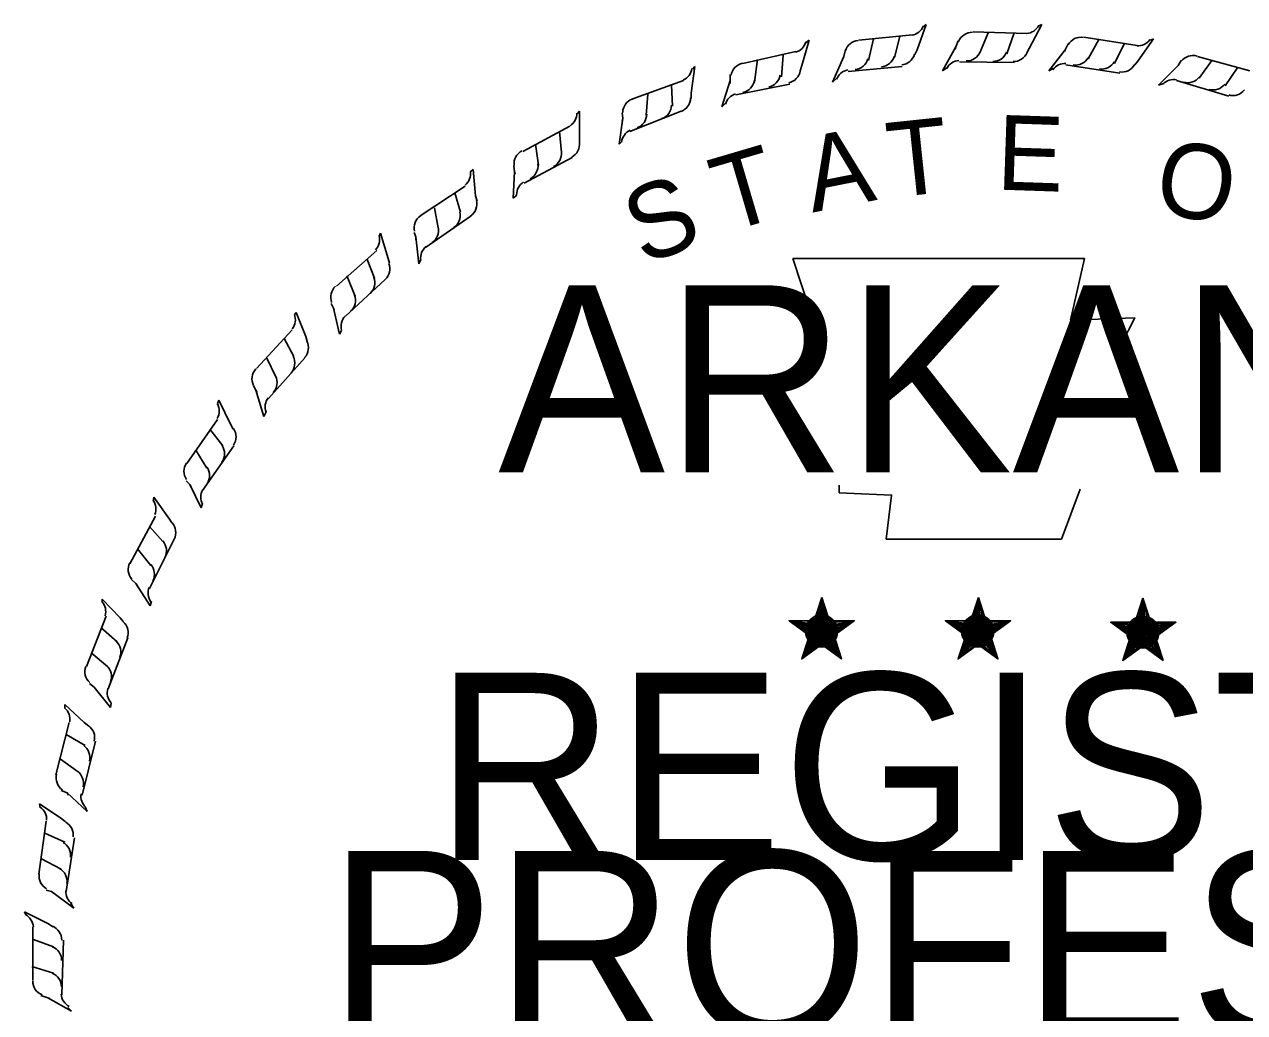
# Model space of a CAD drawing. Extents: x -193 to 149, y 507 to 725.
# Drawn here: x 54.01 to 66.24, y 530.25 to 540.16 of the extents above; entities that cross this region are included whole.
import ezdxf

# ---------------------------------------------------------------- set-up
doc = ezdxf.new("R2010")
doc.units = 0
doc.layers.add('Border 2660-Hwy18 - Stamp-ChrisC', color=7, linetype='Continuous')

msp = doc.modelspace()

# ---------------------------------------------------------------- linework, layer by layer
at = {"layer": 'Border 2660-Hwy18 - Stamp-ChrisC'}
for p, q in [((62.37, 540), (62.91, 540.053)), ((62.73, 539.828), (62.782, 540.038)), ((62.955, 539.903), (63.045, 540.158)), ((63.045, 540.158), (63.015, 540.135)), ((63.517, 540.083), (64.057, 540.068)), ((63.585, 539.873), (63.667, 540.075)), ((63.855, 539.865), (63.93, 540.075)), ((64.08, 539.918), (64.207, 540.158)), ((64.207, 540.158), (64.177, 540.143)), ((61.8, 539.745), (61.875, 540)), ((61.875, 540), (61.845, 539.978)), ((62.467, 539.798), (62.52, 540.015)), ((63.345, 539.933), (63.21, 539.693)), ((63.345, 539.933), (63.337, 539.91)), ((63.367, 539.993), (63.345, 539.933)), ((64.057, 539.873), (64.08, 539.918)), ((64.47, 539.963), (64.44, 539.903)), ((64.627, 540.03), (65.16, 539.948)), ((64.672, 539.813), (64.777, 540.008)), ((64.935, 539.768), (65.032, 539.963)), ((65.167, 539.79), (65.325, 540.015)), ((65.325, 540.015), (65.295, 540)), ((61.207, 539.768), (61.74, 539.888)), ((61.327, 539.58), (61.357, 539.805)), ((61.597, 539.633), (61.612, 539.85)), ((62.22, 539.835), (62.107, 539.58)), ((62.22, 539.835), (62.212, 539.813)), ((62.235, 539.895), (62.22, 539.835)), ((62.932, 539.858), (62.955, 539.903)), ((64.44, 539.903), (64.275, 539.693)), ((64.44, 539.903), (64.432, 539.888)), ((65.602, 539.798), (65.572, 539.745)), ((65.767, 539.835), (66.292, 539.693)), ((65.782, 539.618), (65.91, 539.798)), ((60.69, 539.468), (60.727, 539.738)), ((60.727, 539.738), (60.705, 539.708)), ((61.785, 539.693), (61.8, 539.745)), ((62.805, 539.738), (62.265, 539.685)), ((63.21, 539.693), (63.255, 539.723)), ((63.93, 539.775), (63.382, 539.783)), ((64.275, 539.693), (64.32, 539.715)), ((64.987, 539.67), (64.447, 539.753)), ((65.137, 539.753), (65.167, 539.79)), ((65.572, 539.745), (65.377, 539.55)), ((65.572, 539.745), (65.557, 539.73)), ((66.045, 539.543), (66.172, 539.73)), ((60.097, 539.408), (60.615, 539.595)), ((60.502, 539.34), (60.495, 539.55)), ((61.08, 539.595), (60.997, 539.333)), ((61.08, 539.655), (61.08, 539.595)), ((61.08, 539.595), (61.08, 539.565)), ((61.68, 539.558), (61.14, 539.453)), ((62.107, 539.58), (62.152, 539.618)), ((65.377, 539.55), (65.43, 539.565)), ((66.082, 539.438), (65.557, 539.595)), ((60.24, 539.25), (60.255, 539.46)), ((60.69, 539.415), (60.69, 539.468)), ((60.997, 539.333), (61.035, 539.37)), ((59.572, 539.288), (59.55, 539.265)), ((59.572, 539.025), (59.572, 539.288)), ((60.007, 539.22), (59.97, 538.958)), ((60, 539.273), (60.007, 539.22)), ((60.007, 539.22), (60, 539.19)), ((60.592, 539.288), (60.075, 539.085)), ((59.002, 538.883), (59.475, 539.138)), ((59.392, 538.875), (59.37, 539.085)), ((59.16, 538.748), (59.13, 538.958)), ((59.572, 538.973), (59.572, 539.025)), ((59.97, 538.958), (60, 538.988)), ((59.497, 538.823), (59.017, 538.568)), ((58.507, 538.703), (58.477, 538.68)), ((58.53, 538.44), (58.507, 538.703)), ((58.912, 538.74), (58.92, 538.68)), ((58.92, 538.68), (58.905, 538.418)), ((58.92, 538.68), (58.927, 538.658)), ((57.975, 538.238), (58.425, 538.538)), ((58.38, 538.275), (58.32, 538.47)), ((58.905, 538.418), (58.942, 538.448)), ((58.545, 538.388), (58.53, 538.44)), ((58.485, 538.238), (58.027, 537.923)), ((58.155, 538.118), (58.117, 538.32)), ((57.577, 538.065), (57.562, 538.035)), ((57.652, 537.81), (57.577, 538.065)), ((57.915, 538.073), (57.93, 538.028)), ((57.93, 538.028), (57.96, 537.758)), ((57.93, 538.028), (57.93, 537.998)), ((57.135, 537.533), (57.54, 537.893)), ((57.517, 537.615), (57.442, 537.803)), ((57.667, 537.765), (57.652, 537.81)), ((57.96, 537.758), (57.982, 537.803)), ((57.622, 537.6), (57.225, 537.233)), ((57.322, 537.435), (57.24, 537.638)), ((57.082, 537.36), (57.105, 537.315)), ((56.73, 537.27), (56.715, 537.248)), ((56.827, 537.03), (56.73, 537.27)), ((57.105, 537.315), (57.165, 537.053)), ((57.105, 537.315), (57.112, 537.293)), ((56.332, 536.708), (56.692, 537.098)), ((56.707, 536.828), (56.61, 537.008)), ((56.842, 536.978), (56.827, 537.03)), ((57.165, 537.053), (57.187, 537.09)), ((56.527, 536.625), (56.437, 536.813)), ((56.82, 536.82), (56.452, 536.408)), ((56.302, 536.535), (56.325, 536.49)), ((55.957, 536.393), (55.942, 536.355)), ((56.077, 536.145), (55.957, 536.393)), ((56.325, 536.49), (56.407, 536.228)), ((56.325, 536.49), (56.34, 536.468)), ((56.407, 536.228), (56.43, 536.273)), ((55.635, 535.755), (55.942, 536.198)), ((56.1, 536.1), (56.077, 536.145)), ((55.995, 535.935), (55.867, 536.1)), ((55.837, 535.71), (55.725, 535.89)), ((56.107, 535.935), (55.792, 535.485)), ((55.627, 535.583), (55.665, 535.545)), ((55.665, 535.545), (55.777, 535.313)), ((55.665, 535.545), (55.68, 535.523)), ((55.305, 535.418), (55.297, 535.38)), ((55.462, 535.2), (55.305, 535.418)), ((55.777, 535.313), (55.792, 535.358)), ((55.065, 534.75), (55.32, 535.23)), ((55.485, 535.163), (55.462, 535.2)), ((55.395, 534.975), (55.26, 535.125)), ((55.275, 534.735), (55.14, 534.9)), ((55.507, 534.998), (55.26, 534.503)), ((55.08, 534.593), (55.125, 534.555)), ((55.125, 534.555), (55.267, 534.33)), ((55.125, 534.555), (55.14, 534.533)), ((62.002, 534.413), (61.95, 534.188)), ((62.002, 534.413), (61.965, 534.18)), ((62.002, 534.413), (61.987, 534.18)), ((62.002, 534.075), (62.002, 534.413)), ((62.002, 534.413), (62.062, 534.18)), ((62.002, 534.413), (62.047, 534.18)), ((62.002, 534.413), (62.025, 534.18)), ((63.57, 534.413), (63.51, 534.188)), ((63.57, 534.413), (63.532, 534.18)), ((63.57, 534.413), (63.547, 534.18)), ((63.57, 534.075), (63.57, 534.413)), ((63.57, 534.413), (63.63, 534.18)), ((63.57, 534.413), (63.615, 534.18)), ((63.57, 534.413), (63.585, 534.18)), ((54.967, 534.21), (54.787, 534.398)), ((54.787, 534.398), (54.787, 534.368)), ((55.267, 534.33), (55.282, 534.375)), ((65.22, 534.405), (65.167, 534.173)), ((65.22, 534.405), (65.182, 534.173)), ((65.22, 534.405), (65.205, 534.173)), ((65.22, 534.06), (65.22, 534.405)), ((65.22, 534.405), (65.287, 534.173)), ((65.22, 534.405), (65.272, 534.173)), ((65.22, 534.405), (65.242, 534.173)), ((54.63, 533.723), (54.825, 534.225)), ((54.997, 534.173), (54.967, 534.21)), ((61.672, 534.18), (62.002, 534.075)), ((61.672, 534.18), (61.912, 534.15)), ((61.672, 534.18), (61.912, 534.135)), ((61.672, 534.18), (61.905, 534.12)), ((61.672, 534.18), (61.897, 534.083)), ((61.672, 534.18), (61.897, 534.06)), ((61.672, 534.18), (61.897, 534.038)), ((62.325, 534.18), (62.002, 534.075)), ((62.325, 534.18), (62.04, 534.158)), ((62.325, 534.18), (62.062, 534.128)), ((62.325, 534.18), (62.062, 534.113)), ((62.325, 534.18), (62.122, 534.09)), ((62.325, 534.18), (62.137, 534.083)), ((62.325, 534.18), (62.152, 534.068)), ((63.24, 534.18), (63.57, 534.075)), ((63.24, 534.18), (63.48, 534.15)), ((63.24, 534.18), (63.472, 534.135)), ((63.24, 534.18), (63.472, 534.12)), ((63.24, 534.18), (63.465, 534.083)), ((63.24, 534.18), (63.457, 534.06)), ((63.24, 534.18), (63.457, 534.038)), ((63.892, 534.18), (63.57, 534.075)), ((63.892, 534.18), (63.607, 534.158)), ((63.892, 534.18), (63.622, 534.128)), ((63.892, 534.18), (63.622, 534.113)), ((63.892, 534.18), (63.682, 534.09)), ((63.892, 534.18), (63.697, 534.083)), ((63.892, 534.18), (63.712, 534.068)), ((54.937, 533.97), (54.772, 534.113)), ((61.8, 533.798), (62.002, 534.075)), ((61.8, 533.798), (61.905, 534.053)), ((62.197, 533.798), (62.002, 534.075)), ((62.197, 533.798), (62.07, 534.068)), ((62.197, 533.798), (62.092, 534.068)), ((63.367, 533.798), (63.57, 534.075)), ((63.367, 533.798), (63.472, 534.053)), ((63.765, 533.798), (63.57, 534.075)), ((63.765, 533.798), (63.637, 534.068)), ((63.765, 533.798), (63.66, 534.068)), ((64.897, 534.165), (65.22, 534.06)), ((64.897, 534.165), (65.137, 534.143)), ((64.897, 534.165), (65.137, 534.128)), ((64.897, 534.165), (65.122, 534.105)), ((64.897, 534.165), (65.122, 534.075)), ((64.897, 534.165), (65.115, 534.053)), ((64.897, 534.165), (65.115, 534.03)), ((65.017, 533.783), (65.22, 534.06)), ((65.55, 534.165), (65.22, 534.06)), ((65.422, 533.783), (65.22, 534.06)), ((65.55, 534.165), (65.257, 534.143)), ((65.55, 534.165), (65.28, 534.12)), ((65.55, 534.165), (65.28, 534.105)), ((65.422, 533.783), (65.295, 534.053)), ((65.422, 533.783), (65.317, 534.06)), ((65.55, 534.165), (65.34, 534.083)), ((65.55, 534.165), (65.355, 534.068)), ((65.55, 534.165), (65.37, 534.06)), ((55.042, 534.008), (54.847, 533.498)), ((61.8, 533.798), (61.92, 534.023)), ((61.8, 533.798), (61.935, 534.015)), ((61.8, 533.798), (62.002, 534)), ((61.8, 533.798), (61.965, 533.993)), ((61.8, 533.798), (62.002, 533.97)), ((62.197, 533.798), (62.002, 533.993)), ((62.197, 533.798), (62.002, 533.97)), ((62.197, 533.798), (62.032, 533.993)), ((62.197, 533.798), (62.062, 534.023)), ((63.367, 533.798), (63.48, 534.023)), ((63.367, 533.798), (63.502, 534.015)), ((63.367, 533.798), (63.562, 534)), ((63.367, 533.798), (63.532, 533.993)), ((63.367, 533.798), (63.57, 533.97)), ((63.765, 533.798), (63.562, 533.993)), ((63.765, 533.798), (63.562, 533.97)), ((63.765, 533.798), (63.6, 533.993)), ((63.765, 533.798), (63.63, 534.023)), ((65.017, 533.783), (65.122, 534.038)), ((65.017, 533.783), (65.137, 534.015)), ((65.017, 533.783), (65.16, 534.008)), ((65.017, 533.783), (65.22, 533.985)), ((65.017, 533.783), (65.182, 533.978)), ((65.017, 533.783), (65.227, 533.963)), ((65.422, 533.783), (65.22, 533.985)), ((65.422, 533.783), (65.22, 533.955)), ((65.422, 533.783), (65.257, 533.978)), ((65.422, 533.783), (65.287, 534.015)), ((54.84, 533.723), (54.675, 533.858)), ((54.66, 533.55), (54.705, 533.513)), ((54.705, 533.513), (54.87, 533.31)), ((54.705, 533.513), (54.72, 533.498)), ((54.607, 533.16), (54.412, 533.34)), ((54.412, 533.34), (54.412, 533.303)), ((54.87, 533.31), (54.877, 533.355)), ((54.322, 532.635), (54.457, 533.16)), ((54.652, 533.123), (54.607, 533.16)), ((54.615, 532.928), (54.427, 533.04)), ((54.72, 532.973), (54.585, 532.433)), ((54.547, 532.665), (54.367, 532.793)), ((54.375, 532.478), (54.435, 532.455)), ((54.435, 532.455), (54.637, 532.268)), ((54.435, 532.455), (54.45, 532.433)), ((54.382, 532.193), (54.157, 532.343)), ((54.157, 532.343), (54.165, 532.305)), ((54.637, 532.268), (54.615, 532.313)), ((54.15, 531.638), (54.225, 532.17)), ((54.42, 532.163), (54.382, 532.193)), ((54.412, 531.96), (54.21, 532.05)), ((54.51, 532.005), (54.427, 531.465)), ((54.375, 531.69), (54.172, 531.795)), ((54.225, 531.48), (54.277, 531.465)), ((54.277, 531.465), (54.502, 531.3)), ((54.277, 531.465), (54.3, 531.45)), ((54.247, 531.143), (54.007, 531.263)), ((54.007, 531.263), (54.022, 531.233)), ((54.502, 531.3), (54.472, 531.345)), ((54.09, 530.573), (54.09, 531.113)), ((54.292, 531.113), (54.247, 531.143)), ((54.3, 530.91), (54.097, 530.985)), ((54.397, 530.978), (54.382, 530.43)), ((54.3, 530.648), (54.082, 530.715)), ((54.172, 530.423), (54.24, 530.4)), ((54.24, 530.4), (54.48, 530.265)), ((54.24, 530.4), (54.262, 530.393)), ((54.48, 530.265), (54.442, 530.303))]:
    msp.add_line(p, q, dxfattribs=at)
for points in [[(61.71, 537.81), (61.965, 537.038)], [(65.002, 536.948), (65.137, 537.218), (64.492, 537.195), (64.635, 537.81), (61.71, 537.81)], [(62.175, 535.538), (62.175, 535.463), (62.7, 535.44), (62.647, 534.998), (64.402, 534.998), (64.59, 535.5)], [(62.002, 534.413), (62.197, 533.798), (61.672, 534.18), (62.325, 534.18), (61.8, 533.798), (62.002, 534.413)], [(63.57, 534.413), (63.765, 533.798), (63.24, 534.18), (63.892, 534.18), (63.367, 533.798), (63.57, 534.413)], [(65.22, 534.405), (65.422, 533.783), (64.897, 534.165), (65.55, 534.165), (65.017, 533.783), (65.22, 534.405)]]:
    msp.add_lwpolyline(points, dxfattribs=at)
for centre, radius in [((61.998, 534.076), 0.161), ((61.998, 534.076), 0.146), ((61.998, 534.076), 0.136), ((61.998, 534.076), 0.124), ((61.998, 534.076), 0.109), ((61.998, 534.076), 0.101), ((61.998, 534.076), 0.0929), ((63.563, 534.076), 0.161), ((63.563, 534.076), 0.146), ((63.563, 534.076), 0.136), ((63.563, 534.076), 0.124), ((63.563, 534.076), 0.109), ((63.563, 534.076), 0.101), ((63.563, 534.076), 0.0929), ((65.219, 534.065), 0.161), ((65.219, 534.065), 0.146), ((65.219, 534.065), 0.136), ((65.219, 534.065), 0.124), ((65.219, 534.065), 0.109), ((61.998, 534.076), 0.08), ((61.998, 534.076), 0.0701), ((61.998, 534.076), 0.0583), ((61.998, 534.076), 0.0464), ((61.998, 534.076), 0.0346), ((61.998, 534.076), 0.0278), ((61.998, 534.076), 0.0135), ((63.563, 534.076), 0.08), ((63.563, 534.076), 0.0701), ((63.563, 534.076), 0.0583), ((63.563, 534.076), 0.0464), ((63.563, 534.076), 0.0346), ((63.563, 534.076), 0.0278), ((63.563, 534.076), 0.0135), ((65.219, 534.065), 0.101), ((65.219, 534.065), 0.0929), ((65.219, 534.065), 0.08), ((65.219, 534.065), 0.0701), ((65.219, 534.065), 0.0583), ((65.219, 534.065), 0.0464), ((65.219, 534.065), 0.0346), ((65.219, 534.065), 0.0278), ((65.219, 534.065), 0.0135)]:
    msp.add_circle(centre, radius, dxfattribs=at)
for centre, start, end in [((62.879, 540.196), 279.9249, 338.7128), ((63.508, 539.931), 89.1628, 157.5368), ((64.045, 540.216), 273.4236, 332.2115), ((61.696, 540.021), 286.2701, 345.0579), ((62.378, 539.851), 95.6641, 164.0381), ((64.599, 539.882), 81.4231, 149.797), ((65.169, 540.092), 265.6839, 324.4717), ((62.32, 539.854), 275.6641, 344.0381), ((62.583, 539.879), 275.6641, 344.0381), ((62.787, 539.9), 275.6641, 344.0381), ((63.384, 539.648), 93.4236, 152.2115), ((63.451, 539.94), 269.1628, 337.5368), ((63.716, 539.935), 269.1628, 337.5368), ((63.921, 539.933), 269.1628, 337.5368), ((64.543, 539.899), 261.4231, 329.797), ((65.721, 539.699), 73.9909, 142.3649), ((60.549, 539.733), 294.8371, 353.6249), ((61.236, 539.624), 102.0093, 170.3833), ((61.638, 539.717), 282.0093, 350.3833), ((62.286, 539.556), 99.9249, 158.7128), ((64.437, 539.618), 85.6839, 144.4717), ((64.805, 539.858), 261.4231, 329.797), ((65.008, 539.828), 261.4231, 329.797), ((61.178, 539.62), 282.0093, 350.3833), ((61.437, 539.674), 282.0093, 350.3833), ((65.527, 539.458), 78.2517, 137.0395), ((65.669, 539.722), 253.9909, 322.3649), ((65.923, 539.649), 253.9909, 322.3649), ((61.178, 539.32), 106.2701, 165.0579), ((66.12, 539.593), 253.9909, 322.3649), ((60.153, 539.272), 110.5763, 178.9503), ((60.345, 539.352), 290.5763, 358.9503), ((60.537, 539.424), 290.5763, 358.9503), ((59.398, 539.268), 301.9545, 0.7423), ((60.097, 539.26), 290.5763, 358.9503), ((60.141, 538.963), 114.8371, 173.6249), ((59.424, 538.96), 297.6937, 6.0677), ((59.063, 538.761), 117.6937, 186.0677), ((59.243, 538.864), 297.6937, 6.0677), ((59.008, 538.742), 297.6937, 6.0677), ((58.331, 538.663), 309.1135, 7.9014), ((59.089, 538.453), 121.9545, 180.7423), ((58.395, 538.36), 304.8528, 13.2267), ((58.061, 538.118), 124.8528, 193.2267), ((58.227, 538.243), 304.8528, 13.2267), ((58.01, 538.092), 304.8528, 13.2267), ((57.419, 538), 316.8235, 15.6113), ((58.126, 537.816), 129.1135, 187.9014), ((57.523, 537.709), 312.5627, 20.9367), ((57.372, 537.569), 312.5627, 20.9367), ((57.225, 537.424), 132.5627, 200.9367), ((57.177, 537.391), 312.5627, 20.9367), ((56.575, 537.197), 322.2653, 21.0531), ((57.329, 537.133), 136.8235, 195.6113), ((56.706, 536.917), 318.0045, 26.3785), ((56.569, 536.764), 318.0045, 26.3785), ((56.436, 536.605), 138.0045, 206.3785), ((56.392, 536.568), 318.0045, 26.3785), ((56.568, 536.325), 142.2653, 201.0531), ((55.812, 536.283), 329.9636, 28.7515), ((55.98, 536.024), 325.7028, 34.0768), ((55.865, 535.854), 325.7028, 34.0768), ((55.754, 535.678), 145.7028, 214.0768), ((55.715, 535.636), 325.7028, 34.0768), ((55.922, 535.418), 149.9636, 208.7515), ((55.177, 535.301), 337.2243, 36.0121), ((55.376, 535.065), 332.9635, 41.3375), ((55.283, 534.882), 332.9635, 41.3375), ((55.195, 534.694), 152.9635, 221.3375), ((55.162, 534.647), 332.9635, 41.3375), ((55.395, 534.457), 157.2243, 216.0121), ((54.674, 534.272), 343.6465, 42.4343), ((54.898, 534.059), 339.3857, 47.7597), ((54.826, 533.867), 339.3857, 47.7597), ((54.761, 533.67), 159.3857, 227.7597), ((54.732, 533.62), 339.3857, 47.7597), ((54.985, 533.458), 163.6465, 222.4343), ((54.315, 533.192), 350.445, 49.2329), ((54.563, 533.008), 346.1842, 54.5582), ((54.515, 532.808), 346.1842, 54.5582), ((54.473, 532.605), 166.1842, 234.5582), ((54.451, 532.552), 346.1842, 54.5582), ((54.72, 532.421), 170.445, 229.2329), ((54.082, 532.189), 356.646, 55.4338), ((54.349, 532.032), 352.3852, 60.7592), ((54.322, 531.829), 352.3852, 60.7592), ((54.302, 531.622), 172.3852, 240.7592), ((54.286, 531.567), 352.3852, 60.7592), ((54.569, 531.466), 176.646, 235.4338), ((53.949, 531.102), 3.9474, 62.7352), ((54.233, 530.98), 359.6866, 68.0606), ((54.232, 530.775), 359.6866, 68.0606), ((54.23, 530.51), 359.6866, 68.0606), ((54.239, 530.567), 179.6866, 248.0606), ((54.523, 530.446), 183.9474, 242.7352)]:
    msp.add_arc(centre, 0.148, start, end, dxfattribs=at)

# ---------------------------------------------------------------- texts
for s, rotation, p in [('T', 6.0228, (62.695, 538.421)), ('E', 358.0732, (63.745, 538.503)), ('A', 11.2132, (61.907, 538.271)), ('T', 16.4036, (61.037, 538.068)), ('O', 350.4515, (65.312, 538.278)), ('S', 21.594, (60.212, 537.738))]:
    msp.add_text(s, height=0.75, rotation=rotation, dxfattribs=at).set_placement(p)
for s, height, p in [('ARKANSAS', 1.875, (58.757, 535.668)), ('REGISTERED', 1.875, (58.12, 531.783)), ('PROFESSIONAL', 1.87497, (57.047, 529.998))]:
    msp.add_text(s, height=height, dxfattribs=at).set_placement(p)

doc.saveas('drawing.dxf')
